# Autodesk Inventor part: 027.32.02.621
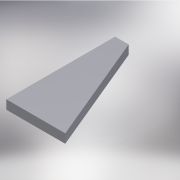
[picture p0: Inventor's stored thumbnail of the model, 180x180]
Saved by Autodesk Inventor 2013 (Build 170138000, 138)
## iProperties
Created: 2005-04
Part Number: 027.32.02.621
Material: Steel, Mild
Document SubType Name: Modeling
Designer: salex
Manufacturer: Standard
Standards Organization: Custom
Density: 7.86 g/cm^3
Author: salex
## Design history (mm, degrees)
sketch "Эскиз1"
  geometry: L1 (0, 0)-(65, 0); L2 (65, 0)-(15, 120); L3 (15, 120)-(0, 120); L4 (0, 120)-(0, 0)
  constraints: 8 end point, 1 horizontal, 1 parallel, 1 perpendicular, 1 other
  dimensions: "d0" = 65 distance of L1.start L1.end; "d1" = 120 distance of L3.end L1.start; "d2" = 15 distance of L2.end L3.end
extrude "Выдавливание1" new body sketch "Эскиз1" distance "d3" = 10; taper "d4" = 0 deg
body "Solid1"
